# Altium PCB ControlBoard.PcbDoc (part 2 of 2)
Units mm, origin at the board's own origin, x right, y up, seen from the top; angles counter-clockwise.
Board outline 111.33 x 150.7 mm, 2 copper layers (Top Layer, Bottom Layer); 147 components, 78 nets, 422 pads, 115 vias.
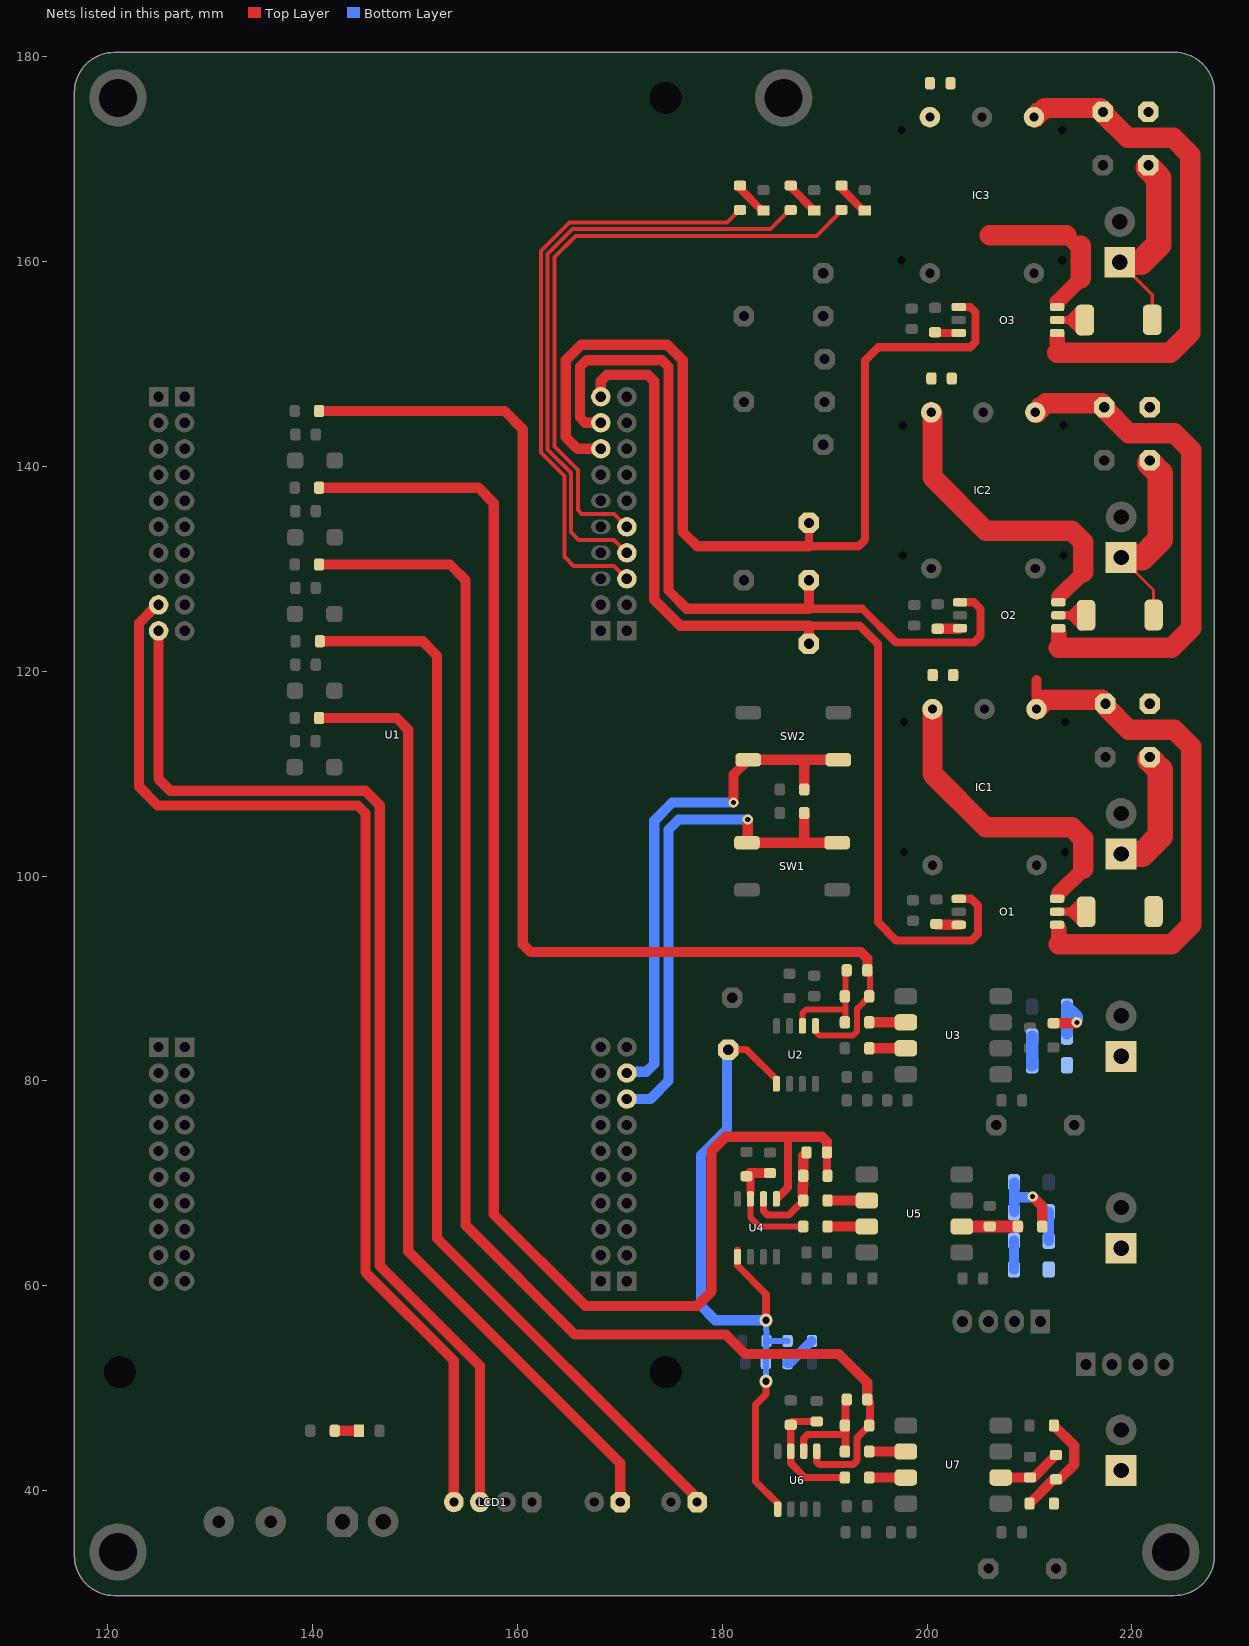
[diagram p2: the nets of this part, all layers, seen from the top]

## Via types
v1: diameter 1, hole 0.4, Top Layer to Bottom Layer, 81 vias
v2: diameter 1, hole 0.5, Top Layer to Bottom Layer, 29 vias
v3: diameter 1.3, hole 0.711, Top Layer to Bottom Layer, 2 vias
v4: diameter 1.27, hole 0.711, Top Layer to Bottom Layer, 1 vias
v5: diameter 1.8, hole 0.8, Top Layer to Bottom Layer, 1 vias
v6: diameter 1.27, hole 0.7, Top Layer to Bottom Layer, 1 vias

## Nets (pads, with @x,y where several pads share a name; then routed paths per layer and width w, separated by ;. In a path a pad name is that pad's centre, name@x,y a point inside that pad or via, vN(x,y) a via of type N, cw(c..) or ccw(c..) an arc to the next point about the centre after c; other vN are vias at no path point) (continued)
NetC12_1: C12.1 R5.2 R19.1 U2.1 | length 117.7
  Top Layer w0.6: U2.1@189.103,85.377 189.103,84.836 189.484,84.455 192.786,84.455 193.167,84.836 193.167,87.074 R19.1@194.358,88.265 ; C12.1@194.183,90.789 194.437,90.535 R19.1@194.437,88.265
  Top Layer w1: R5.2@140.716,145.415 158.75,145.415 160.528,143.637 160.528,93.345 161.29,92.583 193.548,92.583 194.183,91.948 C12.1@194.183,90.789
NetC12_2: C12.2 R18.2 R19.2 U2.2 | length 10.9
  Top Layer w0.6: U2.2@187.833,85.377 187.833,86.614 188.214,86.995 192.024,86.995 ; R18.2@192.024,85.598 192.024,86.995 ; C12.2@192.167,90.805 192.024,90.662 192.024,86.995
NetC18_1: C18.1 R20.1 R25.2 U4.3 | length 11.5
  Top Layer w0.6: U4.3@182.753,68.486 182.753,66.675 183.642,65.786 R25.2@187.912,65.786
  Top Layer w0.8: U4.3@182.753,68.961 R20.1@182.753,70.691
  Top Layer w1: R20.1@182.372,70.691 182.689,71.009 C18.1@184.658,71.009
NetC19_2: C19.2 R24.1 U5.2 | length 5.5
  Top Layer w1.2: U5.2@203.391,65.786 C19.2@206.121,65.786 ; C19.2@206.137,65.786 R24.1@208.867,65.786
  Top Layer w1.5: U5.2@203.327,65.786 U5.2@203.391,65.786
NetC22_1: C22.1 R11.2 R28.1 U4.1 | length 148
  Top Layer w0.8: U4.1@185.42,68.58 186.436,69.596 186.436,74.422 ; C22.1@190.23,73.025 190.246,73.009 R28.1@190.246,70.739
  Top Layer w1: R11.2@140.716,137.922 156.21,137.922 157.702,136.43 157.702,66.961 166.624,58.039 177.546,58.039 178.943,59.436 178.943,73.152 180.34,74.549 186.436,74.549 189.738,74.549 190.23,74.057 C22.1@190.23,73.025
NetC22_2: C22.2 R27.2 R28.2 U4.2 | length 10.7
  Top Layer w0.6: 187.912,69.85 187.96,69.85
  Top Layer w0.7: U4.2@184.023,68.486 184.023,67.31 184.404,66.929 186.515,66.929 R27.2@187.912,68.326
  Top Layer w1: R27.2@187.912,68.374 187.912,68.572 187.872,68.613 187.872,69.85 ; 187.912,69.85 187.872,69.85 ; C22.2@188.23,73.025 187.912,72.707 187.912,69.919 187.872,69.879 187.872,69.85
NetC28_1: C28.1 R32.1 R36.2 U6.3 | length 12.1
  Top Layer w0.7: R32.1@186.69,46.434 U6.3@186.69,43.848 186.69,42.672 188.087,41.275 R36.2@191.897,41.275 ; R32.1@186.69,46.609 186.833,46.752 C28.1@189.23,46.752
NetC30_2: C30.2 R34.1 U7.2 | length 6.6
  Top Layer w1: U7.2@207.137,41.021 207.407,41.291 C30.2@210.058,41.291 ; C30.2@209.931,41.275 210.391,41.275 R34.1@212.598,43.482
NetC31_1: C31.1 R1.2 R42.1 U6.1 | length 136.9
  Top Layer w0.7: U6.1@189.23,43.848 189.23,42.799 189.484,42.545 192.786,42.545 193.167,42.926 193.167,45.164 R42.1@194.358,46.355
  Top Layer w0.8: C31.1@194.167,48.895 194.437,48.625 R42.1@194.437,46.355
  Top Layer w1: R1.2@140.716,130.429 153.416,130.429 154.94,128.905 154.94,65.913 165.608,55.245 180.34,55.245 182.245,53.34 191.389,53.34 194.167,50.562 C31.1@194.167,48.895
NetC31_2: C31.2 R38.2 R42.2 U6.2 | length 10.5
  Top Layer w0.7: U6.2@187.96,43.848 187.96,45.085 188.341,45.466 191.77,45.466
  Top Layer w0.8: R38.2@192.024,43.688 192.024,45.466 192.024,46.355 192.024,48.752 C31.2@192.167,48.895
NetD3_1: D3.1 R3.2 | length 3.4
  Top Layer w0.8: R3.2@191.643,167.434 191.643,167.132 D3.1@193.802,164.973
NetD4_1: D4.1 R4.2 | length 3.4
  Top Layer w0.8: R4.2@186.69,167.434 186.69,167.275 D4.1@188.976,164.989
NetD7_1: D7.1 R7.2 | length 3.4
  Top Layer w0.8: R7.2@181.737,167.434 181.737,167.132 D7.1@183.896,164.973
NetD9_1: D9.1 R41.2 | length 2.4
  Top Layer w1: R41.2@142.161,45.847 D9.1@144.526,45.847
NetLCD1_3: LCD1.3 U1.J1_10 | length 109.2
  Top Layer w1: U1.J1_10@124.968,123.952 124.968,120.269 124.968,109.474 126.111,108.331 145.161,108.331 146.558,106.934 146.558,61.976 156.337,52.197 LCD1.3@156.337,38.887
NetLCD1_4: LCD1.4 U1.J1_9 | length 112.5
  Top Layer w1: U1.J1_9@124.841,126.492 123.063,124.714 123.063,120.142 123.063,108.712 124.873,106.902 144.431,106.902 145.161,106.172 145.161,61.341 153.797,52.705 LCD1.4@153.797,38.887
NetO1_1: O1.1 PWM1.1 U1.J4_10 | length 97.2
  Top Layer w0.8: 188.468,124.46 193.421,124.46 195.199,122.682 195.199,95.504 196.977,93.726 204.343,93.726 204.978,94.361 204.978,97.155 204.343,97.79 O1.1@203.099,97.79
  Top Layer w1: U1.J4_10@168.148,146.812 168.148,148.336 168.783,148.971 172.72,148.971 173.355,148.336 173.355,127 175.895,124.46 188.214,124.46 ; PWM1.1@188.468,122.174 188.468,124.46
NetO1_3: O1.3 R30.2 | length 2.3
  Top Layer w1: R30.2@200.914,95.329 200.993,95.25 O1.3@203.226,95.25
NetO1_5: O1.5 R29.1 | length 5.6
  Top Layer w0.8: O1.5@212.826,96.52 R29.1@215.534,96.52 ; 213.995,96.52 R29.1@215.011,97.536 ; 214.122,96.393 R29.1@215.138,95.377
NetO2_1: O2.1 PWM2.1 U1.J4_9 | length 78.8
  Top Layer w0.8: 188.214,126.111 188.468,126.111 193.675,126.111 196.977,122.809 204.597,122.809 205.232,123.444 205.232,126.111 204.597,126.746 O2.1@203.226,126.746
  Top Layer w1: U1.J4_9@168.148,144.272 166.624,144.272 166.116,144.78 166.116,149.733 166.751,150.368 174.117,150.368 174.752,149.733 174.752,127.889 176.53,126.111 188.214,126.111 ; 188.468,126.111 PWM2.1@188.468,128.905
NetO2_3: O2.3 R37.2 | length 2.1
  Top Layer w1: R37.2@201.041,124.158 O2.3@203.121,124.158
NetO2_5: O2.5 R35.1 | length 5.8
  Top Layer w0.8: O2.5@212.826,125.476 213.995,125.476 ; 214.122,125.349 R35.1@215.138,124.333 ; R35.1@215.265,126.492 215.011,126.492 213.995,125.476 ; R35.1@215.534,125.476 213.995,125.476
NetO3_1: O3.1 PWM3.1 U1.J4_8 | length 95.8
  Top Layer w0.8: PWM3.1@188.468,134.747 188.468,132.207 193.294,132.207 193.929,132.842 193.929,150.368 195.199,151.638 204.216,151.638 204.724,152.146 204.724,155.067 204.216,155.575 O3.1@203.099,155.575
  Top Layer w1: U1.J4_8@168.148,141.732 165.862,141.732 164.719,142.875 164.719,150.368 166.243,151.892 174.625,151.892 176.149,150.368 176.149,133.604 177.546,132.207 188.468,132.207
NetO3_3: O3.3 R44.2 | length 2.4
  Top Layer w0.8: R44.2@200.787,153.114 200.866,153.035 O3.3@203.099,153.035 O3.3@203.2,153.035
NetO3_5: O3.5 R43.1 | length 5.6
  Top Layer w0.8: O3.5@212.699,154.305 R43.1@215.407,154.305 ; 213.868,154.305 R43.1@214.884,155.321 ; 213.995,154.178 R43.1@215.011,153.162
NetP_IBAT_1: P_IBAT.1 R6.2 | length 93.2
  Top Layer w1: R6.2@140.637,115.443 148.209,115.443 149.352,114.3 149.352,63.373 170.053,42.672 P_IBAT.1@170.053,38.887
NetP_IL_1: P_IL.1 R2.2 | length 105.2
  Top Layer w1: R2.2@140.716,122.936 150.749,122.936 152.146,121.539 152.146,64.643 177.546,39.243 P_IL.1@177.546,38.887
NetP_VAC_1: P_VAC.1 R13.1
NetP_VBAT_1: P_VBAT.1 R33.1
NetP_VPFC_1: P_VPFC.1 R21.1
NetR3_1: R3.1 U1.J2_5 | length 61
  Top Layer w0.4: U1.J2_5@170.688,134.112 169.418,135.382 166.278,135.382 165.9,135.76 165.9,139.662 163.614,141.948 163.614,160.439 165.697,162.522 189.192,162.522 R3.1@191.643,164.973
NetR4_1: R4.1 U1.J2_4 | length 59.9
  Top Layer w0.4: U1.J2_4@170.688,131.572 169.418,132.842 165.989,132.842 165.246,133.585 165.246,139.391 162.96,141.677 162.96,160.765 165.371,163.176 184.714,163.176 186.59,165.052 R4.1@186.69,165.052
NetR7_1: R7.1 U1.J2_3 | length 58.7
  Top Layer w0.4: U1.J2_3@170.688,129.032 169.418,130.302 165.481,130.302 164.592,131.191 164.592,139.065 162.306,141.351 162.306,161.036 165.1,163.83 180.467,163.83 R7.1@181.61,164.973
NetR8_1: R8.1 R9.2 | length 3.2
  Bottom Layer w1: R8.1@186.388,52.451 186.563,52.451 R9.2@188.722,54.61
NetR13_2: R13.2 R14.1 | length 3
  Bottom Layer w1: R13.2@210.185,81.407 210.264,81.486 R13.2@210.264,81.534
  Bottom Layer w1.2: R13.2@210.264,81.534 R14.1@210.264,84.328
NetR14_2: R14.2 R15.2 R17.2 | length 6.6
  Top Layer w1: R15.2@212.344,85.646 214.551,85.646 v2(214.63,85.725)
  Bottom Layer w1.2: R14.2@213.662,84.661 R17.2@213.662,87.249 214.63,86.281 v2@214.63,85.979
NetR16_1: R16.1 U3.7 | length 3.5
  Top Layer w1: R16.1@194.358,83.185 U3.7@197.866,83.185
NetR18_1: R18.1 U3.6 | length 3.9
  Top Layer w1: R18.1@194.358,85.725 U3.6@197.929,85.725 198.12,85.725 U3.6@198.247,85.852
NetR21_2: R21.2 R22.1 | length 2.8
  Bottom Layer w1: R21.2@208.486,61.595 R22.1@208.486,64.389
NetR22_2: R22.2 R23.1 | length 2.8
  Bottom Layer w1: R22.2@211.884,64.389 R23.1@211.884,67.183
NetR23_2: R23.2 R24.2 R26.2 | length 7.9
  Top Layer w1: v2(210.312,68.707) 211.249,67.77 R24.2@211.249,65.786
  Bottom Layer w1: R23.2@208.52,67.216 208.52,68.644 ; R26.2@208.52,70.071 208.52,68.644 ; v2@210.248,68.644 208.52,68.644
NetR25_1: R25.1 U5.7 | length 3.9
  Top Layer w1: R25.1@190.294,65.786 U5.7@194.119,65.786 U5.7@194.183,65.786
NetR27_1: R27.1 U5.6 | length 4
  Top Layer w1: R27.1@190.294,68.326 U5.6@194.119,68.326 U5.6@194.31,68.326
NetR29_2: R29.2 SW1.1@221.742,111.633 SWH1.1 | length 12.4
  Top Layer w2.5: SWH1.1@218.948,102.16 221.032,102.16 222.758,103.886 222.758,110.363 SW1.1@221.742,111.379
NetR33_2: R33.2 R34.2 R39.2 | length 10.6
  Top Layer w1: R33.2@210.01,38.735 212.376,41.1 R34.2@212.598,41.1 212.931,41.1 214.376,42.545 214.376,44.371 R39.2@212.392,46.355
NetR35_2: R35.2 SW2.1@221.742,140.589 SWH2.1 | length 19.4
  Top Layer w0.3: SWH2.1@218.948,131.116 222.119,127.945 R35.2@222.119,125.498
  Top Layer w2.5: SWH2.1@218.948,131.116 221.032,131.116 222.758,132.842 222.758,139.319 SW2.1@221.742,140.335
NetR36_1: R36.1 U7.7 | length 3.6
  Top Layer w1: R36.1@194.358,41.275 U7.7@197.929,41.275 U7.7@197.993,41.275
NetR38_1: R38.1 U7.6 | length 3.6
  Top Layer w1: R38.1@194.358,43.815 U7.6@197.929,43.815 U7.6@197.993,43.815
NetR43_2: R43.2 SW3.1 SWH3.1 | length 19.4
  Top Layer w0.3: SWH3.1@218.821,159.945 221.992,156.774 R43.2@221.992,154.327
  Top Layer w2.5: SWH3.1@218.821,159.945 220.905,159.945 222.631,161.671 222.631,168.148 SW3.1@221.615,169.164
NetRB1_2: RB1.2 SW1.1@182.417,103.265 SW1.3 U1.J6_8 | length 51.5
  Top Layer w1: SW1.1@182.417,103.265 188.073,103.265 ; SW1.1@182.499,103.31 v2(182.499,105.537) ; RB1.2@188.008,106.172 188.008,103.33 188.073,103.265 ; 188.087,103.251 188.073,103.265 ; SW1.3@191.262,103.251 191.248,103.265 SW1.3@191.217,103.265 188.073,103.265
  Bottom Layer w1: U1.J6_8@170.688,78.232 172.974,78.232 174.752,80.01 174.752,104.521 175.768,105.537 v2(182.499,105.537)
NetRB2_2: RB2.2 SW2.1@191.344,111.365 SW2.3 U1.J6_9 | length 51.6
  Top Layer w1: v2(181.102,107.188) 181.102,109.923 SW2.3@182.544,111.365 187.974,111.365 ; 187.96,111.379 187.974,111.365 ; RB2.2@188.008,108.458 188.008,111.331 187.974,111.365 ; SW2.1@191.344,111.365 187.974,111.365
  Bottom Layer w1: U1.J6_9@170.815,80.899 172.593,80.899 173.355,81.661 173.355,105.41 175.133,107.188 v2(181.102,107.188)
VDD1: C21.2 IC1.5 O1.6 VDD1.1 | length 30
  Top Layer w1.5: 212.852,98.298 215.265,100.711
  Top Layer w2: IC1.5@200.534,116.311 200.534,109.981 205.74,104.775 214.122,104.775 215.265,103.632 215.265,100.711
VDD2: C29.2 IC2.5 O2.6 VDD2.1 | length 30
  Top Layer w1.5: 212.852,127.254 215.265,129.667
  Top Layer w2: IC2.5@200.534,145.267 200.534,138.937 205.74,133.731 214.122,133.731 215.265,132.588 215.265,129.667
VDD3: C32.2 IC3.5 O3.6 VDD3.1 | length 16.1
  Top Layer w1.5: 212.725,156.083 215.011,158.369 ; 213.614,162.56 215.138,161.036
  Top Layer w2: 206.121,162.56 213.614,162.56 ; 215.011,158.369 215.011,161.539
Vref: C5.2 R9.1 R10.2 U2.5 U4.5 U6.5 Vref.1 | length 69.8
  Top Layer w0.7: Vref.1@180.213,83.058 Vref.1@180.594,83.058 182.372,83.058 185.293,80.137 U2.5@185.293,79.723 ; U4.5@181.483,63.5 U4.5@181.483,62.832 181.483,61.976 184.325,59.135 184.277,59.087 ; v3(184.277,50.673) 184.277,49.403 183.261,48.387 183.261,40.894 185.42,38.735 U6.5@185.42,38.194 ; v3@184.277,56.388 v3(184.277,56.642)
  Top Layer w0.8: v3(184.277,56.642) 184.277,59.087
  Bottom Layer w0.6: v3(184.277,50.673) R10.2@184.277,54.737 ; v3(184.277,56.642) R10.2@184.325,54.61 ; R10.2@184.531,54.61 R9.1@186.388,54.61
  Bottom Layer w1: Vref.1@180.467,83.058 180.467,75.311 177.927,72.771 177.927,58.039 179.324,56.642 v3(184.277,56.642)
VSS1: C21.1 IC1.3 O1.4 VSS1.1 | length 53
  Top Layer w1: 210.677,119.126 210.677,117.221 210.677,116.328 IC1.3@210.694,116.311
  Top Layer w1.5: 212.852,93.345 O1.4@212.852,94.869
  Top Layer w2: IC1.3@210.694,116.311 211.604,117.221 217.043,117.221 VSS1.1@217.424,116.84 217.424,116.586 219.71,114.3 224.155,114.3 225.806,112.649 225.806,95.25 223.901,93.345 212.852,93.345
VSS2: C29.1 IC2.3 O2.4 VSS2.1 | length 51.1
  Top Layer w1: IC2.3@210.677,146.177 210.677,145.284 IC2.3@210.694,145.267
  Top Layer w1.5: 212.852,122.301 O2.4@212.852,123.825
  Top Layer w2: IC2.3@210.694,145.267 211.604,146.177 217.043,146.177 217.424,145.796 217.424,145.542 219.71,143.256 224.155,143.256 225.806,141.605 225.806,124.206 223.901,122.301 212.852,122.301
VSS3: C32.1 IC3.3 O3.4 VSS3.1 | length 51.1
  Top Layer w1: IC3.3@210.55,175.006 210.55,174.113 IC3.3@210.567,174.096
  Top Layer w1.5: 212.725,151.13 O3.4@212.725,152.654
  Top Layer w2: IC3.3@210.567,174.096 211.477,175.006 216.916,175.006 217.297,174.625 217.297,174.371 219.583,172.085 224.028,172.085 225.679,170.434 225.679,153.035 223.774,151.13 212.725,151.13
pads on no net: IC1. IC2. IC3. LO1.1 LO2.1 LO3.1 LO4.1 O1.2 O2.2 O3.2 U1. U1.J1_2 U1.J1_3 U1.J1_4 U1.J1_5 U1.J1_6 U1.J1_7 U1.J1_8 U1.J2_1 U1.J2_2 U1.J2_6 U1.J2_7 U1.J2_8 U1.J2_9 U1.J3_8 U1.J3_9 U1.J3_10 U1.J4_1 U1.J4_2 U1.J4_3 U1.J4_4 U1.J4_5 U1.J4_6 U1.J4_7 U1.J5_1 U1.J5_2 U1.J5_3 U1.J5_4 U1.J5_5 U1.J5_6 U1.J5_7 U1.J5_8 U1.J5_9 U1.J5_10 U1.J6_1 U1.J6_2 U1.J6_3 U1.J6_4 U1.J6_5 U1.J6_6 U1.J6_7 U1.J7_3 U1.J7_4 U1.J7_5 U1.J7_6 U1.J7_7 U1.J7_8 U1.J7_9 U1.J7_10 U1.J8_1 U1.J8_2 U1.J8_3 U1.J8_4 U1.J8_5 U1.J8_6 U1.J8_7 U1.J8_8 U1.J8_9 U1.J8_10

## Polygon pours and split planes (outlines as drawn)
GND on Top Layer "gnda" (solid, pour order 57): 136.906,146.05 136.906,144.018 136.144,143.256 127,143.256 126.492,143.764 126.492,144.78 127,145.288 129.032,145.288 130.175,146.431 130.175,150.876 127.889,153.162 123.444,153.162 120.142,156.464 120.142,168.529 122.809,171.196 179.07,171.196 180.086,170.18 180.086,164.719 179.705,164.338 164.719,164.338 161.671,161.29 161.671,147.828 160.655,146.812 137.668,146.812
GND on Top Layer "gnda" (solid, pour order 59): 145.415,33.909 145.923,33.401 152.527,33.401 153.162,34.036 153.162,36.703 151.892,37.973 151.892,53.086 144.145,60.833 144.145,78.613 144.145,105.41 143.637,105.918 123.317,105.918 122.428,105.029 122.428,91.313 123.952,89.789 127.254,89.789 130.175,86.868 130.175,53.467 136.144,47.498 145.288,47.498 145.923,46.863 145.923,38.354 145.415,37.846
GND on Top Layer "gnda" (solid, pour order 58): 164.211,152.908 164.211,160.274 165.862,161.925 187.96,161.925 187.96,137.16 186.309,135.509 178.435,135.509 177.292,136.652 177.292,150.876 175.26,152.908
GND on Top Layer "gnda" (solid, pour order 56): 184.404,114.046 184.404,116.078 184.658,116.332 189.484,116.332 189.484,113.03 189.103,112.649 185.801,112.649
GND on Top Layer "gnda" (solid, pour order 55): 189.992,109.855 193.167,109.855 193.421,109.601 193.421,104.775 190.119,104.775 189.738,105.156 189.738,109.601
GND on Top Layer "gnda" (solid, pour order 47): 140.081,143.891 157.988,143.891 158.877,143.002 158.877,139.319 140.081,139.319 139.827,139.573 139.827,143.637
GND on Top Layer "gnda" (solid, pour order 51): 139.954,113.919 147.193,113.919 147.701,113.411 147.701,109.347 139.954,109.347 139.7,109.601 139.7,113.665
GND on Top Layer "gnda" (solid, pour order 50): 140.081,121.412 149.606,121.412 150.622,120.396 150.622,116.84 140.081,116.84 139.827,117.094 139.827,121.158
GND on Top Layer "gnda" (solid, pour order 49): 140.081,128.905 152.4,128.905 153.162,128.143 153.162,124.333 140.081,124.333 139.827,124.587 139.827,128.651
GND on Top Layer "gnda" (solid, pour order 48): 140.081,136.398 155.448,136.398 156.083,135.763 156.083,131.826 140.081,131.826 139.827,132.08 139.827,136.144
GND on Top Layer "gnda" (solid, pour order 46): 193.675,81.026 194.564,81.026 195.707,81.026 195.961,80.772 195.961,79.629 196.723,78.867 196.723,75.565 196.469,75.311 192.659,75.311 192.405,75.565 192.405,76.454 193.421,77.47 193.421,80.772
GND on Top Layer "gnda" (solid, pour order 45): 195.58,91.44 198.755,91.44 199.009,91.186 199.009,87.63 198.755,87.376 195.58,87.376 195.326,87.63 195.326,91.186
GND on Top Layer "gnda" (solid, pour order 43): 189.865,63.754 191.008,63.754 193.167,61.595 193.167,57.531 192.913,57.277 188.849,57.277 188.595,57.531 188.595,58.928 189.611,59.944 189.611,63.5
GND on Top Layer "gnda" (solid, pour order 42): 191.77,74.041 194.945,74.041 195.199,73.787 195.199,70.231 194.945,69.977 191.77,69.977 191.516,70.231 191.516,73.787
GND on Top Layer "gnda" (solid, pour order 41): 195.834,49.53 198.755,49.53 199.009,49.276 199.009,45.72 198.755,45.466 195.834,45.466 195.58,45.72 195.58,49.276
GND on Top Layer "gnda" (solid, pour order 40): 193.675,39.116 194.564,39.116 196.469,37.211 196.723,37.211 196.977,36.957 196.977,33.655 196.723,33.401 192.659,33.401 192.405,33.655 192.405,34.544 193.421,35.56 193.421,38.862
GNDA on Top Layer "gnda" (solid, pour order 21): 224.155,90.805 206.629,90.805 205.613,89.789 205.613,87.249 205.613,85.598 206.502,84.709 210.566,84.709 210.82,84.963 210.82,86.487 211.582,87.249 215.773,87.249 216.408,86.614 216.408,85.217 216.789,84.836 221.361,84.836 222.25,83.947 222.25,80.264 221.361,79.375 209.55,79.375 208.788,78.613 208.788,74.422 207.899,73.533 201.93,73.533 201.549,73.152 201.549,67.691 201.93,67.31 208.534,67.31 208.915,67.691 208.915,69.469 209.423,69.977 211.328,69.977 212.471,68.834 212.471,66.167 212.471,64.77 211.709,64.008 205.994,64.008 204.978,62.992 204.978,58.928 204.98,55.624 205.344,55.258 206.634,55.252 207.001,55.614 207.016,58.174 207.775,58.928 215.011,58.928 216.281,60.198 216.281,65.532 216.916,66.167 223.901,66.167 225.425,67.691 225.425,89.535
GNDB on Top Layer "gnda" (solid, pour order 35): 221.742,53.34 221.488,53.594 219.71,53.594 219.456,53.34 219.456,50.546 218.44,49.53 205.867,49.53 205.232,48.895 205.232,43.436 205.859,42.805 207.055,42.799 210.566,42.799 210.947,43.18 210.947,46.99 211.455,47.498 213.36,47.498 215.773,45.085 216.408,44.45 220.98,44.45 221.742,43.688 221.742,40.005 220.98,39.243 216.535,39.243 214.122,36.83 209.169,36.83 208.788,36.449 208.788,31.496 208.788,31.242 209.55,30.48 219.202,30.48 220.091,31.369 220.091,35.433 224.917,40.259 224.917,44.45 224.917,48.895 224.282,49.53 222.758,49.53 221.742,50.546
NetP_VBAT_1 on Top Layer "gnda" (solid, pour order 36): 216.408,43.434 220.472,43.434 220.472,40.386 220.091,40.005 215.773,40.005 213.741,37.973 211.963,37.973 211.836,38.1 211.836,39.243 211.963,39.37 213.106,39.37 216.027,42.291 216.027,43.053
VSS3 on Top Layer "VSS1" (solid, pour order 28): 208.915,172.593 209.55,171.958 218.44,171.958 219.202,172.72 219.202,177.292 218.44,178.054 201.803,178.054 201.803,176.149 202.057,175.895 208.407,175.895 208.915,175.387
VDD3 on Top Layer "vdd3" (solid, pour order 27): 198.12,177.419 198.12,163.322 200.025,161.417 215.773,161.417 216.027,161.671 216.027,162.306 214.757,163.576 205.994,163.576 202.184,167.386 202.184,174.879 201.803,175.26 201.168,175.26 200.787,175.641 200.787,178.054 199.39,178.054 198.755,178.054
VDD2 on Top Layer "VSS1" (solid, pour order 26): 198.247,148.59 198.247,134.493 200.152,132.588 215.9,132.588 216.154,132.842 216.154,133.477 214.884,134.747 206.121,134.747 202.311,138.557 202.311,146.05 201.93,146.431 201.295,146.431 200.914,146.812 200.914,149.225 199.517,149.225 198.882,149.225
VSS2 on Top Layer "VSS1" (solid, pour order 25): 209.042,143.764 209.677,143.129 218.567,143.129 219.329,143.891 219.329,148.463 218.567,149.225 201.93,149.225 201.93,147.32 202.184,147.066 208.534,147.066 209.042,146.558
COM1 on Top Layer "VSS1" (solid, pour order 24): 203.835,117.602 207.899,117.602 208.407,117.094 208.407,114.427 209.296,113.538 217.678,113.538 219.329,111.887 219.329,109.982 220.472,108.839 220.472,105.537 219.583,104.648 218.186,104.648 216.154,106.68 206.883,106.68 203.327,110.236 203.327,117.094
VDD1 on Top Layer "VSS1" (solid, pour order 2): 198.374,119.634 198.374,105.537 200.279,103.632 216.027,103.632 216.281,103.886 216.281,104.521 215.011,105.791 206.248,105.791 202.438,109.601 202.438,117.094 202.057,117.475 201.422,117.475 201.041,117.856 201.041,120.269 199.644,120.269 199.009,120.269
VSS1 on Top Layer "VSS1" (solid, pour order 0): 209.169,114.808 209.804,114.173 218.694,114.173 219.456,114.935 219.456,119.507 218.694,120.269 202.057,120.269 202.057,118.364 202.311,118.11 208.661,118.11 209.169,117.602
NetR29_2 on Top Layer "VSS1" (solid, pour order 4): 217.297,103.759 220.345,103.759 221.488,104.902 221.488,109.982 224.028,109.982 224.028,103.759 224.028,95.885 223.012,94.869 218.44,94.869 217.297,96.012
COM2 on Top Layer "VSS1" (solid, pour order 8): 203.708,146.558 207.772,146.558 208.28,146.05 208.28,143.383 209.169,142.494 217.551,142.494 219.202,140.843 219.202,138.938 220.345,137.795 220.345,134.493 219.456,133.604 218.059,133.604 216.027,135.636 206.756,135.636 203.2,139.192 203.2,146.05
NetR35_2 on Top Layer "VSS1" (solid, pour order 9): 217.297,132.715 220.345,132.715 221.488,133.858 221.488,138.938 224.028,138.938 224.028,132.715 224.028,124.841 223.012,123.825 218.44,123.825 217.297,124.968
VDD3 on Top Layer "VSS1" (solid, pour order 12): 198.12,175.387 198.12,163.322 200.025,161.417 215.773,161.417 216.027,161.671 216.027,162.306 214.757,163.576 205.994,163.576 202.184,167.386 202.184,175.387
COM3 on Top Layer "VSS1" (solid, pour order 13): 203.581,175.387 207.645,175.387 208.153,174.879 208.153,172.212 209.042,171.323 217.424,171.323 219.075,169.672 219.075,167.767 220.218,166.624 220.218,163.322 219.329,162.433 217.932,162.433 215.9,164.465 206.629,164.465 203.073,168.021 203.073,174.879
NetR43_2 on Top Layer "VSS1" (solid, pour order 15): 217.17,161.544 220.218,161.544 221.361,162.687 221.361,167.767 223.901,167.767 223.901,161.544 223.901,153.67 222.885,152.654 218.313,152.654 217.17,153.797
GND on Bottom Layer "gnda" (solid, pour order 53): 124.968,171.323 183.388,171.323 194.945,171.323 196.85,169.418 196.85,162.052 195.326,160.528 186.309,160.528 183.388,157.607 183.388,117.348 179.324,113.284 124.841,113.284 120.142,117.983 120.142,166.497
GND on Bottom Layer "gnda" (solid, pour order 54): 195.326,160.782 191.77,160.782 191.77,121.285 189.992,119.507 183.388,119.507 177.165,113.284 185.42,113.284 185.42,105.918 183.642,104.14 177.8,104.14 176.53,102.87 176.784,102.616 176.784,93.726 193.929,93.726 195.326,95.123
GND on Bottom Layer "gnda" (solid, pour order 22): 194.183,73.914 180.34,73.914 178.943,72.517 178.943,58.928 179.959,57.912 185.674,57.912 186.436,57.15 198.755,57.15 199.263,57.658 199.263,60.198 198.628,60.833 195.961,60.833 195.199,61.595 195.199,72.898
GND on Bottom Layer "gnda" (solid, pour order 52): 124.968,107.823 169.799,107.823 172.466,105.156 172.466,45.72 178.562,39.624 178.562,33.528 126.365,33.528 120.142,39.751 120.142,102.997
GND on Bottom Layer "gnda" (solid, pour order 44): 198.247,91.44 180.721,91.44 179.959,90.678 179.959,86.995 180.848,86.106 182.626,86.106 183.515,85.217 183.515,76.454 184.531,75.438 198.12,75.438 199.009,76.327 199.009,78.994 199.009,90.678
GND on Bottom Layer "gnda" (solid, pour order 39): 198.247,49.53 183.769,49.53 182.88,48.641 182.88,33.401 197.993,33.401 199.009,34.417 199.009,37.084 199.009,48.768
GND on Bottom Layer "gnda" (solid, pour order 38): 210.185,57.658 215.9,57.658 216.408,57.15 216.408,51.181 216.027,50.8 198.374,50.8 198.374,54.61 210.185,54.61
GNDA on Bottom Layer "VSS1" (solid, pour order 20): 223.52,67.437 223.52,89.408 222.123,90.805 208.915,90.805 208.407,90.297 208.407,86.741 208.788,86.36 210.947,86.36 211.328,86.741 211.328,88.392 211.836,88.9 214.503,88.9 216.281,87.122 216.281,85.344 216.789,84.836 221.234,84.836 221.615,84.455 221.615,78.74 220.98,78.105 213.487,78.105 212.979,77.597 212.979,73.278 212.345,72.644 205.994,72.644 204.978,71.628 204.978,66.167 204.978,55.626 205.359,55.245 206.629,55.245 207.01,55.626 207.01,66.167 207.01,70.867 207.519,71.374 209.296,71.374 209.804,70.866 209.804,70.104 210.058,69.85 210.947,69.85 211.328,69.469 211.327,68.962 211.709,68.579 213.108,68.578 213.487,68.199 213.484,66.551 213.868,66.167 218.551,66.167 222.25,66.167
NetP_VAC_1 on Bottom Layer "VSS1" (solid, pour order 34): 220.472,83.947 220.472,79.883 219.964,79.375 213.36,79.375 212.979,79.756 212.979,82.169 213.36,82.55 214.503,82.55 214.757,82.804 214.757,83.566 215.138,83.947 217.424,83.947
VDD3 on Bottom Layer "gnda" (solid, pour order 32): 201.803,172.593 198.882,172.593 198.374,173.101 198.374,177.419 199.009,178.054 223.012,178.054 223.647,177.419 223.647,172.974 223.012,172.339 219.456,172.339 218.821,172.974 218.821,175.514 218.313,176.022 202.946,176.022 202.311,175.387 202.311,173.101
VDD2 on Bottom Layer "gnda" (solid, pour order 31): 201.93,143.764 199.009,143.764 198.501,144.272 198.501,148.59 199.136,149.225 223.139,149.225 223.774,148.59 223.774,144.145 223.139,143.51 219.583,143.51 218.948,144.145 218.948,146.685 218.44,147.193 203.073,147.193 202.438,146.558 202.438,144.272
COM3 on Bottom Layer "VSS1" (solid, pour order 30): 203.581,175.387 207.645,175.387 208.153,174.879 208.153,172.212 209.042,171.323 217.424,171.323 219.075,169.672 219.075,167.767 220.218,166.624 220.218,163.322 219.329,162.433 217.932,162.433 215.9,164.465 206.629,164.465 203.073,168.021 203.073,174.879
COM2 on Bottom Layer "VSS1" (solid, pour order 29): 203.708,146.558 207.772,146.558 208.28,146.05 208.28,143.383 209.169,142.494 217.551,142.494 219.202,140.843 219.202,138.938 220.345,137.795 220.345,134.493 219.456,133.604 218.059,133.604 216.027,135.636 206.756,135.636 203.2,139.192 203.2,146.05
COM1 on Bottom Layer "VSS1" (solid, pour order 3): 203.835,117.602 207.899,117.602 208.407,117.094 208.407,114.427 209.296,113.538 217.678,113.538 219.329,111.887 219.329,109.982 220.472,108.839 220.472,105.537 219.583,104.648 218.186,104.648 216.154,106.68 206.883,106.68 203.327,110.236 203.327,117.094
VDD1 on Bottom Layer "gnda" (solid, pour order 23): 201.93,114.808 199.009,114.808 198.501,115.316 198.501,119.634 199.136,120.269 223.139,120.269 223.774,119.634 223.774,115.189 223.139,114.554 219.583,114.554 218.948,115.189 218.948,117.729 218.44,118.237 203.073,118.237 202.438,117.602 202.438,115.316
NetP_VPFC_1 on Bottom Layer "VSS1" (solid, pour order 19): 220.472,65.151 220.472,61.087 219.964,60.579 211.455,60.579 211.201,60.833 211.201,62.357 211.455,62.611 212.725,62.611 213.487,63.373 213.487,64.643 213.995,65.151 217.424,65.151

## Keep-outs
Keep-Out Layer:
  lines w0.2: 227.965,176.53 ccw(c224.155,176.53) 224.155,180.34 120.65,180.34 ccw(c120.65,176.53) 116.84,176.53 116.84,33.655 ccw(c120.65,33.655) 120.65,29.845 224.155,29.845 ccw(c224.155,33.655) 227.965,33.655 227.965,176.657

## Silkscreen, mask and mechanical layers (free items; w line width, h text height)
Top Overlay:
  text "-" at 226.206,163.291 h1.5 r90
  text "+" at 226.214,159.354 h1.5 r90
  text "-" at 226.333,134.462 h1.5 r90
  text "+" at 226.341,130.525 h1.5 r90
  text "-" at 226.333,105.506 h1.5 r90
  text "+" at 226.341,101.569 h1.5 r90
  text "-" at 226.333,85.821 h1.5 r90
  text "+" at 226.341,81.884 h1.5 r90
  text "-" at 226.333,67.025 h1.5 r90
  text "+" at 226.341,63.088 h1.5 r90
  text "-" at 226.333,45.308 h1.5 r90
  text "+" at 135.501,43.934 h3
  text "-" at 130.294,43.665 h3
  text "+" at 226.341,41.371 h1.5 r90
  text "-" at 167.594,34.717 h1.2 r180
  text "-" at 175.087,34.717 h1.2 r180
  text "+" at 170.515,34.698 h1.2 r180
  text "+" at 178.008,34.698 h1.2 r180
  text "SCL" at 152.6,33.728 h0.8
  text "SDA" at 155.521,33.728 h0.8
  text "+" at 158.542,33.628 h1.2
  text "-" at 160.574,33.482 h1.2
  text "+" at 143.872,31.858 h1.5 r180
  text "-" at 147.174,31.612 h1.5 r180
  text "-" at 130.221,30.479 h1
  text "5V" at 134.92,30.399 h1
Bottom Overlay:
  text "ctrinh01028485@gmail.com" at 152.489,171.023 h1.5 r90
  text "19502231" at 146.412,170.923 h1.5 r90
  text "Trinh Cong" at 149.468,170.923 h1.5 r90
  text "X5.14" at 140.813,170.15 h5 r90
  text "IUH, 2019 - 2023" at 160,145.923 h1.6 r90
  text "INDUSTRIAL UNIVERSITY OF HOCHIMINH CITY / POWER ELECTRONICS APPLICATIONS LAB" at 152.654,102.489 h1.5 r90
  text "IUHPEAL" at 143.415,99.346 h8 r90
  text "Dr. Tan-Tai Tran" at 160,70.612 h1.6 r90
